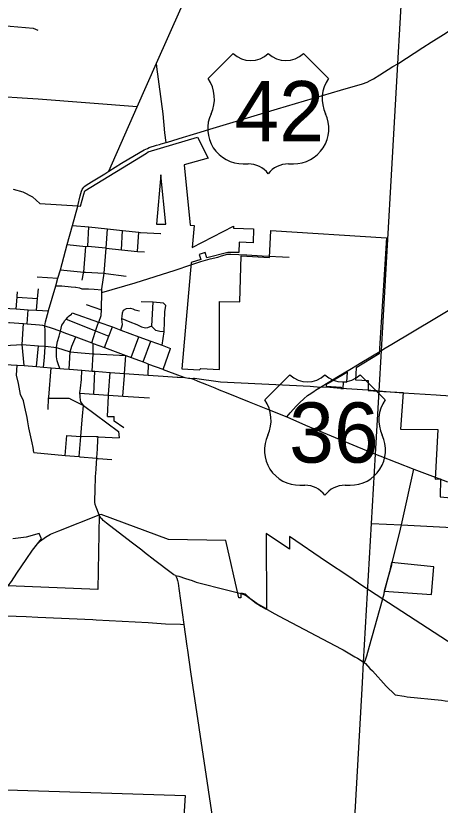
# Model space of a CAD drawing. Extents: x 1729596 to 1925846, y 659247 to 911751.
# Drawn here: x 1811952 to 1821771, y 827504 to 845758 of the extents above; entities that cross this region are included whole.
import ezdxf

# ---------------------------------------------------------------- set-up
doc = ezdxf.new("R2010")
doc.units = 0
for name, color, linetype in [('GM_X_City_Street', 7, 'Continuous'), ('GM_X_Corporation', 7, 'Continuous'), ('GM_X_County_Road', 7, 'Continuous'), ('GM_X_State_Route', 7, 'Continuous'), ('GM_X_Township', 7, 'Continuous'), ('GM_X_Township_Road', 7, 'Continuous'), ('GM_X_US_Route', 7, 'Continuous'), ('GM_X_US_Shield', 7, 'Continuous')]:
    doc.layers.add(name, color=color, linetype=linetype)

msp = doc.modelspace()

# ---------------------------------------------------------------- linework, layer by layer
at = {"layer": 'GM_X_City_Street'}
for points in [[(1813264, 840905), (1813642, 840880), (1814074, 840832), (1814423, 840793), (1814796, 840753), (1814833, 840749), (1814836, 840748)], [(1813621, 840431), (1813642, 840880)], [(1813944, 839395), (1813944, 839420), (1813945, 839445), (1813997, 839807), (1814043, 840388), (1814074, 840832)], [(1814399, 840349), (1814423, 840793)], [(1814768, 840308), (1814796, 840753)], [(1814836, 840748), (1815302, 840727), (1815310, 840726)], [(1813144, 840466), (1813572, 840423), (1813621, 840431), (1814038, 840389)], [(1813521, 839810), (1813525, 839832), (1813572, 840423)], [(1814038, 840389), (1814043, 840388), (1814399, 840349), (1814768, 840308), (1814772, 840307), (1814773, 840307)], [(1814773, 840307), (1814931, 840297)], [(1812984, 839887), (1813525, 839832), (1813562, 839830)], [(1813943, 839357), (1814716, 839584), (1815637, 839875), (1816002, 840001), (1816050, 840016)], [(1812448, 839720), (1812928, 839694)], [(1813487, 839645), (1813521, 839810)], [(1813562, 839830), (1813997, 839807), (1814036, 839802)], [(1814036, 839802), (1814508, 839740)], [(1811984, 839274), (1811992, 839372)], [(1812435, 838949), (1812458, 839219), (1812477, 839441)], [(1812877, 839516), (1813015, 839510), (1813234, 839491)], [(1813234, 839491), (1813336, 839482)], [(1813336, 839482), (1813340, 839482), (1813426, 839467), (1813481, 839444), (1813596, 839443), (1813638, 839442)], [(1813638, 839442), (1813769, 839438), (1813944, 839420)], [(1813804, 838489), (1813859, 838649), (1813870, 838676), (1813928, 838824), (1813933, 838957), (1813934, 838997), (1813942, 839347), (1813943, 839357), (1813944, 839395)], [(1811960, 838979), (1811982, 839250), (1811983, 839262), (1811984, 839274)], [(1811982, 839250), (1812458, 839219)], [(1811488, 839018), (1811817, 838990), (1811960, 838979), (1812235, 838959), (1812435, 838949), (1812709, 838939)], [(1813584, 839080), (1813933, 838957)], [(1814381, 838492), (1814421, 838620), (1814408, 838745), (1814409, 838757), (1814412, 838803), (1814421, 838887), (1814444, 838949), (1814516, 838992), (1814608, 838999), (1814662, 838979), (1814710, 838960), (1814812, 838933)], [(1815336, 838141), (1815384, 838451), (1815399, 838913), (1815423, 839061), (1815369, 839114), (1815134, 839137), (1814855, 839144)], [(1815384, 838451), (1815281, 838455), (1815189, 838484), (1815161, 838508), (1815102, 838575), (1815103, 838587), (1815134, 839137)], [(1812216, 838633), (1812235, 838959)], [(1812978, 838434), (1812985, 838465), (1813020, 838602), (1813060, 838667), (1813083, 838707), (1813116, 838739), (1813128, 838751), (1813160, 838786), (1813190, 838818), (1813243, 838856), (1813260, 838889)], [(1813260, 838889), (1813869, 838676)], [(1812101, 838154), (1812128, 838640)], [(1813116, 838739), (1813798, 838472), (1814106, 838352)], [(1813869, 838676), (1813870, 838676), (1814189, 838564), (1814381, 838492), (1814798, 838338), (1815074, 838236), (1815336, 838141), (1815339, 838139), (1815535, 838067)], [(1814409, 838757), (1814591, 838679), (1814754, 838617), (1814862, 838568), (1814952, 838539), (1815010, 838552), (1815103, 838587)], [(1812896, 838093), (1812917, 838230), (1812953, 838352), (1812972, 838412), (1812978, 838434)], [(1813710, 838195), (1813788, 838442), (1813793, 838457), (1813798, 838472), (1813804, 838489)], [(1814002, 838086), (1814106, 838352), (1814189, 838564)], [(1813186, 837584), (1813195, 837718), (1813211, 837984), (1813251, 838122), (1813340, 838332)], [(1814621, 837856), (1814798, 838338)], [(1811382, 838163), (1811697, 838134), (1812101, 838154), (1812475, 838127), (1812630, 838122), (1812636, 838121)], [(1812144, 837672), (1812101, 838154)], [(1812429, 837651), (1812475, 838127)], [(1812636, 838121), (1812896, 838091), (1813211, 837984), (1813466, 837967), (1813742, 837940), (1813767, 837939)], [(1812968, 837602), (1812932, 837713), (1812910, 837782), (1812893, 837871), (1812896, 838091), (1812896, 838093)], [(1813723, 837544), (1813742, 837940), (1813746, 838181)], [(1814899, 837753), (1815074, 838236)], [(1815358, 837582), (1815535, 838067)], [(1813767, 837939), (1814499, 837901)], [(1814464, 837437), (1814468, 837489), (1814499, 837901)], [(1815015, 837449), (1815024, 837706)], [(1812366, 835662), (1812354, 835774), (1812332, 835884), (1812301, 836023), (1812256, 836232), (1812234, 836365), (1812214, 836466), (1812161, 836711), (1812128, 836854), (1812061, 836997), (1812015, 837252), (1811967, 837444), (1811981, 837682)], [(1812713, 836937), (1812771, 837620)], [(1813448, 837149), (1813474, 837346), (1813478, 837560)], [(1813756, 837010), (1813782, 837540)], [(1814098, 837003), (1814136, 837513)], [(1814427, 836964), (1814464, 837437)], [(1816021, 837368), (1816062, 837380), (1816090, 837381), (1816690, 837295), (1818762, 837191), (1819004, 837172)], [(1813437, 837046), (1813439, 837082), (1813448, 837149)], [(1819004, 837172), (1819134, 837175), (1819472, 837149)], [(1813443, 836943), (1813440, 836977), (1813437, 837031), (1813437, 837046)], [(1813437, 837031), (1813756, 837010), (1814097, 836986), (1814427, 836964), (1815045, 836922)], [(1814071, 836491), (1814096, 836972), (1814097, 836986), (1814098, 837003)], [(1819524, 837145), (1819604, 837139), (1820097, 837105)], [(1812698, 836652), (1812711, 836919), (1812713, 836937)], [(1812711, 836919), (1813181, 836918), (1813206, 836905)], [(1813206, 836905), (1813208, 836904), (1813516, 836746)], [(1813495, 836498), (1813516, 836746), (1813459, 836830), (1813448, 836868), (1813448, 836873), (1813443, 836943)], [(1813516, 836746), (1814331, 836146), (1814342, 835995)], [(1813815, 836021), (1813457, 836033), (1813488, 836416), (1813495, 836498)], [(1814071, 836491), (1814230, 836491)], [(1814453, 836230), (1814230, 836387), (1814230, 836491)], [(1813094, 835594), (1813134, 836056)], [(1813134, 836056), (1813457, 836033)], [(1813418, 835564), (1813457, 836033)], [(1813833, 835648), (1813839, 835738), (1813852, 835957), (1813856, 836020), (1813815, 836021)], [(1813856, 836020), (1814342, 835995)], [(1812366, 835662), (1813094, 835594), (1813418, 835564), (1813418, 835564)], [(1813418, 835564), (1813431, 835563), (1813825, 835527), (1813852, 835524)], [(1813809, 835287), (1813825, 835527), (1813826, 835538), (1813833, 835648)], [(1813852, 835524), (1813857, 835524), (1814177, 835494)], [(1813880, 834222), (1813811, 834398), (1813791, 834454), (1813780, 834509), (1813779, 834575), (1813791, 834764), (1813798, 835121), (1813801, 835169), (1813809, 835287)], [(1820652, 833075), (1820849, 833886), (1820873, 833984), (1820908, 834123), (1821164, 835274)], [(1812457, 833548), (1812466, 833559), (1812525, 833614), (1812643, 833705), (1812759, 833772), (1812946, 833851), (1813880, 834222)], [(1817072, 832421), (1817099, 832415), (1817170, 832396)], [(1820438, 832263), (1820471, 832388), (1820478, 832416)]]:
    msp.add_lwpolyline(points, dxfattribs=at)
at = {"layer": 'GM_X_Corporation'}
for points in [[(1811890, 841751), (1812117, 841685), (1812341, 841568), (1812507, 841420), (1813391, 841360), (1813449, 841356), (1813529, 841637), (1813550, 841711), (1814974, 842584), (1815016, 842610), (1816153, 842951), (1816403, 842466), (1815846, 842310), (1815989, 840914), (1816080, 840907), (1816036, 840400), (1816992, 840894), (1816992, 840847), (1817454, 840834), (1817443, 840510), (1817122, 840521), (1817110, 840282), (1816854, 840287), (1816369, 840160), (1816334, 840281), (1816195, 840241), (1816230, 840120), (1816007, 840055), (1815797, 837596), (1816204, 837568), (1816230, 837602), (1816665, 837580), (1816663, 839149), (1817135, 839141), (1817168, 840204), (1817823, 840172), (1817852, 840795), (1820532, 840624), (1820362, 837942), (1819824, 837620), (1819808, 837343), (1820104, 837324), (1820105, 837097), (1820468, 837073), (1820915, 837044), (1820852, 836201), (1821717, 836195), (1821656, 835046), (1821781, 835050), (1821769, 834633), (1822268, 834587)], [(1824031, 829939), (1819982, 832569), (1819654, 832789), (1819142, 833130), (1818281, 833718), (1818286, 833421), (1817747, 833788), (1817756, 832046), (1817667, 832094), (1817528, 832169), (1817473, 832209), (1817387, 832271), (1817263, 832384), (1817160, 832409), (1817160, 832297), (1817114, 832297), (1816814, 833623), (1815483, 833646), (1813930, 834229), (1813880, 834222), (1813853, 832491), (1811776, 832575)], [(1811850, 832675), (1811974, 832866), (1812189, 833183), (1812337, 833398), (1812545, 833665), (1812495, 833790), (1812189, 833704), (1811881, 833666)], [(1811009, 827882), (1815869, 827729), (1815809, 826748)]]:
    msp.add_lwpolyline(points, dxfattribs=at)
for points in [[(1815210, 840939), (1815427, 840939), (1815307, 842084)], [(1819526, 837135), (1819535, 837296), (1819609, 837287), (1819623, 837519), (1819182, 837253), (1819135, 837235), (1819132, 837195), (1819476, 837173), (1819474, 837138)], [(1820476, 832454), (1821573, 832377), (1821623, 833012), (1820645, 833115), (1820621, 833009), (1820595, 832898)]]:
    msp.add_lwpolyline(points, close=True, dxfattribs=at)
at = {"layer": 'GM_X_County_Road'}
for points in [[(1814101, 842164), (1814760, 843649), (1815210, 844662), (1816320, 847160), (1816351, 847229), (1816426, 847398), (1816452, 847455)], [(1819472, 837149), (1819494, 837147), (1819524, 837145)], [(1820097, 837105), (1820163, 837101), (1820305, 837091)], [(1820305, 837091), (1820358, 837087), (1820517, 837071), (1820825, 837049)], [(1820825, 837049), (1820913, 837042), (1821680, 836994), (1821777, 836987), (1822028, 836972), (1822074, 836969)], [(1813910, 834164), (1813898, 834183), (1813880, 834222)], [(1815650, 832818), (1815609, 832834), (1815550, 832877), (1815172, 833164), (1814933, 833350), (1814868, 833401), (1814625, 833586), (1814048, 834029), (1813975, 834088), (1813947, 834115), (1813922, 834145), (1813910, 834164)], [(1815650, 832818), (1815681, 832754), (1815696, 832701), (1815707, 832636), (1815724, 832514), (1815839, 831685), (1815910, 831182), (1815924, 831087), (1815997, 830585), (1816596, 826570), (1816611, 826462)]]:
    msp.add_lwpolyline(points, dxfattribs=at)
at = {"layer": 'GM_X_State_Route'}
for points in [[(1820468, 838053), (1820655, 838166), (1821648, 838759), (1824240, 840319)], [(1811786, 838666), (1811806, 838664), (1812128, 838640), (1812216, 838633), (1812504, 838609), (1812573, 838603), (1812621, 838591)], [(1812621, 838591), (1812791, 838538), (1812839, 838519), (1812985, 838465), (1813129, 838411)], [(1813129, 838411), (1813340, 838332), (1813710, 838195), (1813746, 838181), (1814002, 838086), (1814499, 837901), (1814621, 837856), (1814811, 837785), (1814899, 837753), (1814979, 837723), (1815024, 837706), (1815354, 837583), (1815358, 837582), (1815752, 837432), (1815862, 837391)], [(1819182, 837279), (1819382, 837398), (1819716, 837599), (1819921, 837722), (1820411, 838018), (1820468, 838053)], [(1818870, 837089), (1818887, 837100), (1819004, 837172), (1819182, 837279)], [(1818616, 836904), (1818704, 836977), (1818742, 837004), (1818870, 837089)], [(1818221, 836484), (1818267, 836536), (1818298, 836577), (1818447, 836739), (1818522, 836815), (1818613, 836902), (1818616, 836904)]]:
    msp.add_lwpolyline(points, dxfattribs=at)
at = {"layer": 'GM_X_Township'}
for points in [[(1820182, 834021), (1820274, 835623), (1820357, 837080), (1820411, 838018), (1820789, 844650), (1820950, 847472), (1821204, 851968), (1821306, 853784), (1821743, 860915)], [(1818544, 806864), (1818726, 809558), (1818800, 810798), (1818859, 811418), (1818898, 811871), (1818966, 812859), (1819169, 816826), (1819403, 820562), (1819571, 823253), (1819973, 830336), (1820000, 830812), (1820182, 834021), (1820873, 833984), (1824840, 833781)]]:
    msp.add_lwpolyline(points, dxfattribs=at)
at = {"layer": 'GM_X_Township_Road'}
for points in [[(1811246, 845551), (1811821, 845515), (1812356, 845471), (1812460, 845427)], [(1815429, 842831), (1815402, 843055), (1815358, 843488), (1815219, 844581), (1815210, 844662)], [(1814760, 843649), (1812473, 843830), (1812103, 843852), (1811628, 843882), (1811145, 843912)], [(1816050, 840016), (1816237, 840077), (1816448, 840141), (1816624, 840179), (1816708, 840206), (1816793, 840229), (1816843, 840243), (1816931, 840248), (1817301, 840230), (1817654, 840208), (1818276, 840179)], [(1811766, 832565), (1811850, 832675), (1811974, 832866), (1812189, 833183), (1812337, 833398), (1812457, 833548)], [(1820478, 832416), (1820578, 832795), (1820650, 833063), (1820652, 833075)], [(1815650, 832818), (1815723, 832800), (1815882, 832749), (1816035, 832698), (1816127, 832661), (1816854, 832473), (1817072, 832421)], [(1817170, 832396), (1817189, 832391), (1817247, 832372), (1817293, 832347), (1817314, 832333), (1817347, 832309), (1817435, 832240), (1817523, 832171), (1817551, 832151), (1817625, 832105), (1817729, 832048)], [(1820010, 830806), (1820037, 830840), (1820072, 830957), (1820135, 831180), (1820436, 832256), (1820438, 832263)], [(1817729, 832048), (1817764, 832029), (1817942, 831931), (1818048, 831874), (1819478, 831120), (1819525, 831094), (1819797, 830932), (1819854, 830901), (1819916, 830867), (1820000, 830812), (1820010, 830806)], [(1811732, 831884), (1812190, 831865), (1812461, 831851), (1813734, 831797), (1813810, 831792), (1815017, 831728), (1815419, 831700), (1815762, 831691), (1815839, 831685)], [(1820010, 830806), (1820042, 830778), (1820145, 830662), (1820205, 830609), (1820524, 830257), (1820580, 830196), (1820656, 830123), (1820728, 830055), (1820936, 830023), (1821010, 830011), (1821798, 829929), (1821888, 829919), (1822885, 829807), (1822989, 829796), (1823040, 829782), (1823095, 829767), (1823466, 829565), (1823529, 829531), (1824286, 829155), (1824340, 829128), (1824755, 828908)]]:
    msp.add_lwpolyline(points, dxfattribs=at)
at = {"layer": 'GM_X_US_Route'}
for points in [[(1815985, 842997), (1816140, 843045), (1816516, 843159), (1818004, 843604), (1819466, 844036), (1819970, 844186), (1820078, 844226), (1820154, 844261), (1820230, 844302), (1820378, 844395), (1820678, 844582), (1820789, 844650), (1821371, 845021), (1821564, 845146), (1821850, 845326), (1822366, 845660), (1822875, 845990), (1823392, 846332), (1823964, 846703), (1824557, 847070), (1825025, 847354), (1825562, 847681), (1826103, 848010), (1826523, 848267)], [(1815834, 842951), (1815888, 842967), (1815985, 842997)], [(1815275, 842785), (1815313, 842796), (1815429, 842831), (1815459, 842839), (1815834, 842951)], [(1814014, 842107), (1814057, 842133), (1814101, 842164), (1814401, 842347), (1814829, 842608), (1814925, 842661), (1814996, 842693), (1815038, 842710), (1815205, 842764), (1815275, 842785)], [(1813390, 841357), (1813391, 841360), (1813443, 841596), (1813471, 841705), (1813486, 841739), (1813500, 841764), (1813527, 841798), (1813550, 841820), (1813583, 841843), (1813704, 841918), (1814014, 842107)], [(1812711, 838945), (1812877, 839516), (1812928, 839694), (1812984, 839887), (1813144, 840466), (1813264, 840905), (1813390, 841357)], [(1812629, 838113), (1812630, 838122), (1812634, 838480), (1812621, 838591), (1812637, 838682), (1812709, 838939), (1812711, 838945)], [(1812596, 837635), (1812618, 837856), (1812629, 838113)], [(1811563, 837706), (1811981, 837682), (1812144, 837672), (1812429, 837651), (1812596, 837635)], [(1812596, 837635), (1812771, 837620), (1812968, 837602), (1813063, 837594)], [(1813063, 837594), (1813186, 837584), (1813478, 837560), (1813723, 837544), (1813782, 837540), (1814136, 837513), (1814468, 837489), (1815015, 837449), (1815359, 837423), (1815684, 837401), (1815707, 837400)], [(1815707, 837400), (1815862, 837391)], [(1815862, 837391), (1815950, 837382), (1815954, 837381)], [(1815954, 837381), (1815981, 837378), (1816021, 837368), (1816060, 837353), (1816163, 837312), (1816361, 837232), (1816558, 837152)], [(1816558, 837152), (1816658, 837111), (1816823, 837044), (1817348, 836830), (1817814, 836649), (1818221, 836484)], [(1818221, 836484), (1818657, 836290), (1819840, 835798), (1820274, 835623), (1820373, 835583), (1821164, 835274), (1821658, 835092), (1821742, 835058)], [(1821742, 835058), (1821837, 835019), (1821938, 834981)]]:
    msp.add_lwpolyline(points, dxfattribs=at)
at = {"layer": 'GM_X_US_Shield'}
for p, q in [((1816981, 844887), (1816401, 844307)), ((1816981, 844887), (1816401, 844307)), ((1819186, 844307), (1818606, 844887)), ((1819186, 844307), (1818606, 844887)), ((1817213, 842334), (1817329, 842334)), ((1817213, 842334), (1817329, 842334)), ((1818258, 842334), (1818374, 842334)), ((1818258, 842334), (1818374, 842334)), ((1818293, 837455), (1817713, 836875)), ((1818293, 837455), (1817713, 836875)), ((1820497, 836875), (1819917, 837455)), ((1820497, 836875), (1819917, 837455)), ((1818525, 834903), (1818641, 834903)), ((1818525, 834903), (1818641, 834903)), ((1819569, 834903), (1819685, 834903)), ((1819569, 834903), (1819685, 834903))]:
    msp.add_line(p, q, dxfattribs=at)
for centre, radius, start, end in [((1817387, 845301), 580, 225.573, 314.427), ((1817387, 845301), 580, 225.573, 314.427), ((1818200, 845301), 580, 225.573, 314.427), ((1818200, 845301), 580, 225.573, 314.427), ((1815736, 843841), 812, 334.5471, 35.0009), ((1815736, 843841), 812, 334.5471, 35.0009), ((1819851, 843841), 812, 144.9991, 205.4529), ((1819851, 843841), 812, 144.9991, 205.4529), ((1817204, 843147), 812, 154.8319, 270.6383), ((1817204, 843147), 812, 154.8319, 270.6383), ((1818383, 843147), 812, 269.3617, 25.1681), ((1818383, 843147), 812, 269.3617, 25.1681), ((1817329, 841754), 580, 36.8699, 90), ((1817329, 841754), 580, 36.8699, 90), ((1818258, 841754), 580, 90, 143.1301), ((1818258, 841754), 580, 90, 143.1301), ((1818699, 837870), 580, 225.573, 314.427), ((1818699, 837870), 580, 225.573, 314.427), ((1819511, 837870), 580, 225.573, 314.427), ((1819511, 837870), 580, 225.573, 314.427), ((1817047, 836409), 812, 334.5471, 35.0009), ((1817047, 836409), 812, 334.5471, 35.0009), ((1821162, 836409), 812, 144.9991, 205.4529), ((1821162, 836409), 812, 144.9991, 205.4529), ((1818516, 835715), 812, 154.8319, 270.6383), ((1818516, 835715), 812, 154.8319, 270.6383), ((1819694, 835715), 812, 269.3617, 25.1681), ((1819694, 835715), 812, 269.3617, 25.1681), ((1818641, 834323), 580, 36.8699, 90), ((1818641, 834323), 580, 36.8699, 90), ((1819569, 834323), 580, 90, 143.1301), ((1819569, 834323), 580, 90, 143.1301)]:
    msp.add_arc(centre, radius, start, end, dxfattribs=at)

# ---------------------------------------------------------------- texts
for s, p in [('42', (1817010, 842857)), ('42', (1817010, 842857)), ('36', (1818277, 835425)), ('36', (1818277, 835425))]:
    msp.add_text(s, height=1392.2, dxfattribs=at).set_placement(p)

doc.saveas('drawing.dxf')
